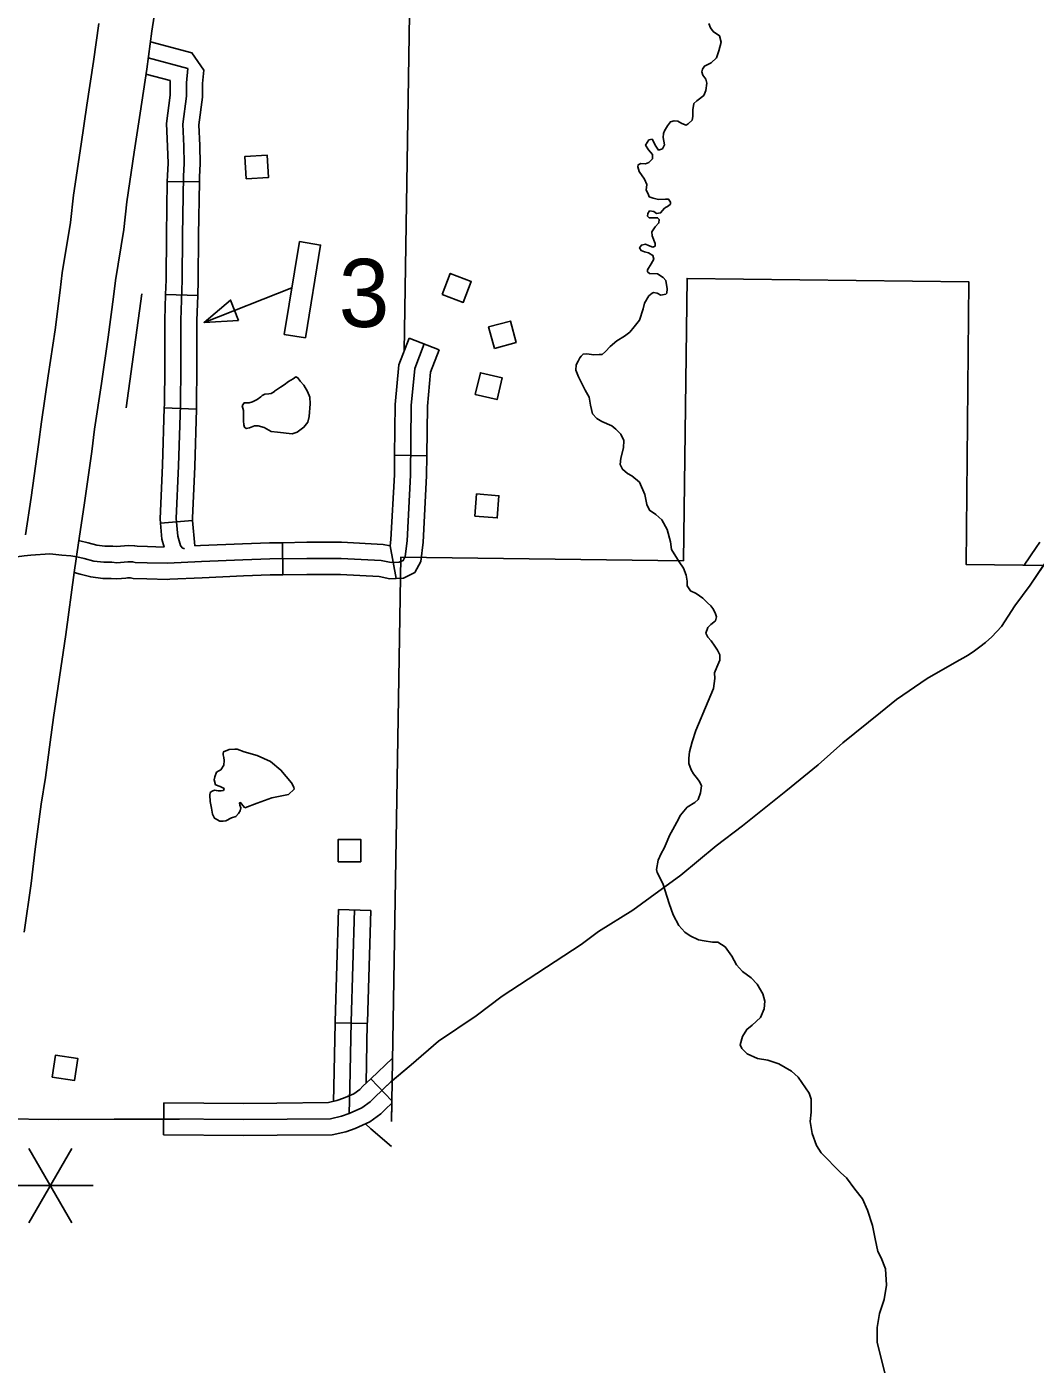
# Model space of a CAD drawing. Extents: x 61396 to 64680, y 55472 to 57605.
# Drawn here: x 63058.6 to 63205.3, y 56330.1 to 56524.6 of the extents above; entities that cross this region are included whole.
import ezdxf

# ---------------------------------------------------------------- set-up
doc = ezdxf.new("R2010")
doc.units = 0
for name, color, linetype in [('15', 7, 'Continuous'), ('31', 7, 'Continuous'), ('32', 7, 'Continuous'), ('33', 7, 'Continuous'), ('34', 7, 'Continuous'), ('35', 7, 'Continuous'), ('48', 7, 'Continuous'), ('5', 7, 'Continuous'), ('56', 7, 'Continuous'), ('6', 7, 'Continuous')]:
    doc.layers.add(name, color=color, linetype=linetype)

msp = doc.modelspace()

# ---------------------------------------------------------------- linework, layer by layer
at = {"layer": '15'}
for points in [[(63077.66, 56529.26), (63076.83, 56523.94), (63076.08, 56518.41), (63075.12, 56512.02), (63074.28, 56506.36), (63073.17, 56499.11), (63072.75, 56495.1), (63071.54, 56487.7), (63071.26, 56485.31), (63070.5, 56479.43), (63069.5, 56472.69), (63068.5, 56466.07), (63068.09, 56462.8), (63067, 56455.01), (63066.17, 56449.55), (63065.55, 56445.21), (63064.3, 56436.22), (63063.21, 56428.7), (63062.51, 56424.15), (63062.06, 56420.57), (63061.38, 56415.43), (63060.75, 56411.55), (63059.85, 56404.97), (63059.27, 56400.01), (63058.26, 56392.9)], [(63058.44, 56450.7), (63059.27, 56456.14), (63060.35, 56463.83), (63060.77, 56467.14), (63061.77, 56473.84), (63062.76, 56480.5), (63063.51, 56486.27), (63063.8, 56488.8), (63065.01, 56496.14), (63065.42, 56500.11), (63066.56, 56507.52), (63067.39, 56513.17), (63068.34, 56519.52), (63069.1, 56525.07)]]:
    msp.add_lwpolyline(points, dxfattribs=at)
at = {"layer": '31'}
msp.add_line((63078.55, 56368.11), (63078.51, 56363.42), dxfattribs=at)
for points in [[(63205.95, 56449.65), (63205.45, 56448.88), (63203.71, 56446.31), (63209.33, 56446.24)], [(63046.7, 56442.08), (63047.5, 56442.34), (63048.97, 56443.14), (63052.37, 56445.59), (63053.66, 56446.32), (63054.54, 56446.81), (63055.19, 56447.16), (63055.94, 56447.34), (63056.52, 56447.43), (63057.21, 56447.52), (63058.25, 56447.65), (63059.23, 56447.72), (63061.99, 56447.93)], [(63105.55, 56366.56), (63107.36, 56367.35), (63108.6, 56368.25), (63109.17, 56368.84), (63111.58, 56371.13), (63114.52, 56373.62), (63118.5, 56377.08), (63124, 56380.77), (63127.78, 56383.63), (63139.28, 56391.14), (63141.77, 56392.99), (63146.79, 56396.12), (63149.29, 56397.97), (63153.75, 56401.18), (63158.89, 56405.48), (63162.71, 56408.38), (63169.02, 56413.4), (63173.73, 56417.26), (63177.34, 56420.47), (63182.81, 56424.85), (63185.14, 56426.74), (63189.6, 56429.79), (63193.54, 56432.08), (63195.55, 56433.21), (63196.48, 56433.81), (63197.24, 56434.41), (63198.09, 56435.06), (63199.01, 56435.86), (63200.38, 56437.35), (63202.35, 56440.36), (63204.56, 56443.37), (63207.41, 56447.59)], [(63108.67, 56371.6), (63111.84, 56374.6)], [(63108.67, 56371.6), (63107.52, 56370.51), (63107.06, 56370.03), (63106.19, 56369.4), (63104.69, 56368.75), (63103.74, 56368.41), (63102.51, 56368.13), (63095.01, 56368.06)], [(63111.73, 56368.04), (63111.74, 56368.38), (63108.67, 56371.6)], [(63105.55, 56366.56), (63107.36, 56367.35), (63108.6, 56368.25), (63109.17, 56368.84), (63111.78, 56371.32)], [(63095.01, 56368.06), (63090.19, 56368.01), (63078.55, 56368.11)], [(63095.05, 56363.37), (63103.06, 56363.45), (63105.05, 56363.9), (63106.41, 56364.38), (63108.53, 56365.31), (63110.14, 56366.48), (63110.82, 56367.17), (63111.73, 56368.04)], [(63078.53, 56365.77), (63090.2, 56365.66), (63102.79, 56365.79)], [(63102.79, 56365.79), (63104.4, 56366.15), (63105.55, 56366.56)], [(63102.79, 56365.79), (63104.4, 56366.15), (63105.55, 56366.56)], [(63078.51, 56363.42), (63090.2, 56363.32), (63095.05, 56363.37)]]:
    msp.add_lwpolyline(points, dxfattribs=at)
at = {"layer": '32'}
for p, q in [((63076.3, 56520.06), (63082.05, 56518.52)), ((63079.07, 56502.11), (63083.76, 56502.03)), ((63078.82, 56485.65), (63083.51, 56485.49)), ((63114.25, 56479.31), (63118.62, 56477.62)), ((63078.64, 56469.15), (63083.33, 56469)), ((63112.13, 56462.27), (63116.82, 56462.21)), ((63078.09, 56452.39), (63082.76, 56452.78)), ((63095.81, 56449.56), (63095.86, 56444.88)), ((63111.5, 56449.09), (63112.38, 56444.35)), ((63103.98, 56396.22), (63108.66, 56396.08)), ((63103.48, 56379.71), (63108.16, 56379.61))]:
    msp.add_line(p, q, dxfattribs=at)
for points in [[(63076.62, 56522.4), (63082.66, 56520.78), (63084.39, 56518.3)], [(63075.97, 56517.72), (63079.51, 56516.77)], [(63082.05, 56518.52), (63081.86, 56516.43), (63081.86, 56514.48), (63081.33, 56510.43), (63081.48, 56507.24), (63081.52, 56504.72), (63081.43, 56502.86), (63081.29, 56494.29), (63081.24, 56487.73), (63081.05, 56481.92), (63081.05, 56475.11), (63081, 56469.59), (63080.71, 56460.74), (63080.38, 56453.07), (63080.6, 56450.51), (63081.01, 56449.13), (63081.25, 56448.83), (63081.56, 56448.67)], [(63084.39, 56518.3), (63084.2, 56516.32), (63084.2, 56514.33), (63083.68, 56510.33), (63083.82, 56507.32), (63083.87, 56504.68), (63083.77, 56502.78), (63083.76, 56502.03)], [(63079.51, 56516.77), (63079.51, 56514.63), (63078.98, 56510.53), (63079.13, 56507.17), (63079.18, 56504.76), (63079.09, 56502.94), (63079.07, 56502.11)], [(63079.07, 56502.11), (63078.94, 56494.32), (63078.89, 56487.77), (63078.82, 56485.65)], [(63083.76, 56502.03), (63083.63, 56494.27), (63083.58, 56487.68), (63083.51, 56485.49)], [(63078.82, 56485.65), (63078.7, 56481.96), (63078.7, 56475.12), (63078.66, 56469.64), (63078.64, 56469.15)], [(63083.51, 56485.49), (63083.39, 56481.88), (63083.39, 56475.1), (63083.34, 56469.54), (63083.33, 56469)], [(63114.25, 56479.31), (63112.76, 56475.44), (63112.22, 56469.66), (63112.13, 56462.27)], [(63116.44, 56478.46), (63115.06, 56474.9), (63114.56, 56469.53), (63114.44, 56459.36), (63113.94, 56449.84), (63113.69, 56447.56), (63113.38, 56446.99), (63112.81, 56446.71), (63111.65, 56446.67), (63110.16, 56446.97), (63104.34, 56447.26), (63099.37, 56447.26), (63093.99, 56447.2), (63090.08, 56447.07), (63084.03, 56446.81), (63079.12, 56446.56), (63076.15, 56446.65), (63074.42, 56446.69), (63074.02, 56446.78), (63073.33, 56446.79)], [(63118.62, 56477.62), (63117.37, 56474.36), (63116.91, 56469.41), (63116.82, 56462.21)], [(63078.64, 56469.15), (63078.37, 56460.83), (63078.03, 56453.03), (63078.09, 56452.39)], [(63083.33, 56469), (63083.06, 56460.65), (63082.73, 56453.12), (63082.76, 56452.78)], [(63112.13, 56462.27), (63112.1, 56459.43), (63111.6, 56450.02), (63111.5, 56449.09)], [(63116.82, 56462.21), (63116.78, 56459.28), (63116.28, 56449.65), (63115.97, 56446.83), (63115.07, 56445.22), (63113.41, 56444.39), (63112.38, 56444.35)], [(63078.09, 56452.39), (63078.28, 56450.06), (63078.63, 56448.92)], [(63082.76, 56452.78), (63083.07, 56449.11)], [(63066.21, 56449.84), (63066.35, 56449.83), (63067.57, 56449.53), (63068.85, 56449.2), (63069.99, 56449.05), (63071.14, 56449.05), (63071.76, 56448.99), (63073.37, 56449.13)], [(63095.81, 56449.56), (63093.94, 56449.54), (63089.99, 56449.41), (63083.92, 56449.16), (63083.07, 56449.11)], [(63111.5, 56449.09), (63110.45, 56449.3), (63104.4, 56449.61), (63099.36, 56449.61), (63095.81, 56449.56)], [(63061.99, 56447.93), (63063.76, 56447.74), (63065.05, 56447.63), (63065.93, 56447.52), (63067, 56447.26), (63068.4, 56446.89), (63069.84, 56446.71), (63071.02, 56446.71), (63071.76, 56446.63), (63073.33, 56446.79)], [(63078.63, 56448.92), (63076.2, 56449), (63074.7, 56449.03), (63074.31, 56449.12), (63073.37, 56449.13)], [(63065.55, 56445.2), (63066.43, 56444.99), (63067.95, 56444.58), (63069.69, 56444.36), (63070.9, 56444.36), (63071.76, 56444.28), (63073.74, 56444.44)], [(63079.47, 56444.23), (63079.15, 56444.21), (63076.09, 56444.31), (63074.13, 56444.35), (63073.74, 56444.44), (63073.29, 56444.44)], [(63095.86, 56444.88), (63094.04, 56444.86), (63090.17, 56444.73), (63084.14, 56444.47), (63079.47, 56444.23)], [(63112.38, 56444.35), (63111.46, 56444.32), (63109.87, 56444.64), (63104.28, 56444.92), (63099.39, 56444.92), (63095.86, 56444.88)], [(63103.98, 56396.22), (63103.48, 56379.93), (63103.48, 56379.71)], [(63106.32, 56396.15), (63105.83, 56379.87), (63105.62, 56370.31), (63105.55, 56366.56)], [(63108.66, 56396.08), (63108.17, 56379.81), (63108.16, 56379.61)], [(63103.48, 56379.71), (63103.28, 56370.35), (63103.24, 56368.29)], [(63108.16, 56379.61), (63107.98, 56370.94)]]:
    msp.add_lwpolyline(points, dxfattribs=at)
at = {"layer": '33'}
for points in [[(63206.52, 56446.27), (63204.56, 56443.37), (63202.35, 56440.36), (63200.38, 56437.35), (63199.01, 56435.86), (63198.09, 56435.06), (63197.24, 56434.41), (63196.48, 56433.81), (63195.55, 56433.21), (63193.54, 56432.08), (63189.6, 56429.79), (63185.14, 56426.74), (63182.81, 56424.85), (63177.34, 56420.47), (63173.73, 56417.26), (63169.02, 56413.4), (63162.71, 56408.38), (63158.89, 56405.48), (63153.75, 56401.18), (63149.29, 56397.97), (63146.79, 56396.12), (63141.77, 56392.99), (63139.28, 56391.14), (63127.78, 56383.63), (63124, 56380.77), (63118.5, 56377.08), (63114.52, 56373.62), (63111.78, 56371.3)], [(63050.7, 56365.95), (63051.63, 56365.89), (63052.75, 56365.86), (63054.55, 56365.76), (63063.27, 56365.66), (63071.35, 56365.72), (63080.84, 56365.74)]]:
    msp.add_lwpolyline(points, dxfattribs=at)
at = {"layer": '34'}
msp.add_lwpolyline([(63107.88, 56365.02), (63108.66, 56364.32), (63111.66, 56361.75)], dxfattribs=at)
at = {"layer": '35'}
for points in [[(63157.84, 56525.07), (63158.06, 56524.42), (63158.44, 56523.92), (63159.36, 56523.28), (63159.65, 56522.34), (63159.28, 56521.11), (63158.95, 56520.05), (63158.15, 56519.35), (63157.19, 56518.87), (63156.91, 56518.43), (63156.82, 56518.02), (63156.98, 56517.55), (63157.42, 56516.99), (63157.55, 56516.4), (63157.41, 56515.33), (63157.11, 56514.61), (63156.27, 56513.95), (63156.11, 56513.82), (63155.65, 56513.41), (63155.5, 56512.5), (63155.51, 56511.56), (63155.43, 56511.02), (63154.84, 56510.49), (63154.53, 56510.3), (63153.9, 56510.54), (63153.3, 56510.85), (63152.77, 56510.93), (63152.24, 56510.77), (63151.81, 56510.2), (63151.38, 56509.45), (63151.24, 56509.09), (63151.19, 56508.51), (63151.4, 56507.44), (63151.07, 56506.82), (63150.53, 56506.65), (63150.12, 56507.23), (63149.58, 56508.22), (63149.09, 56508.14)], [(63149.09, 56508.14), (63148.64, 56507.35), (63149.07, 56506.69), (63149.63, 56505.99), (63149.63, 56505.38), (63149.11, 56504.86), (63148.6, 56504.67), (63147.94, 56504.72), (63147.56, 56504.53), (63147.52, 56504.2), (63147.7, 56503.54), (63148.5, 56502.42), (63148.83, 56501.66), (63148.74, 56500.82), (63149.02, 56500.3), (63149.16, 56499.88), (63149.72, 56499.64), (63150.52, 56499.46), (63151.51, 56499.5), (63151.98, 56499.5), (63152.26, 56499.08), (63152.26, 56498.8), (63151.98, 56498.56), (63151.37, 56498.19), (63150.81, 56497.53), (63150.2, 56497.44), (63149.82, 56497.72), (63149.21, 56497.81), (63148.97, 56497.44), (63148.93, 56497.06), (63149.16, 56496.78), (63149.68, 56496.78), (63150.38, 56496.82), (63150.62, 56496.54), (63150.57, 56496.07), (63150.01, 56495.51), (63149.54, 56494.76), (63149.58, 56494.19), (63150.05, 56493.06), (63150.01, 56492.69), (63149.68, 56492.55), (63149.07, 56492.78), (63148.6, 56492.97), (63148.03, 56492.83), (63147.75, 56492.45), (63147.99, 56492.03), (63148.5, 56491.84), (63149.07, 56491.7), (63149.68, 56491.33), (63149.82, 56490.81), (63149.44, 56490.1), (63148.92, 56489.26), (63148.93, 56488.93)], [(63148.93, 56488.93), (63149.19, 56488.7), (63150.39, 56488.66), (63151.21, 56488.12), (63151.6, 56487.67), (63151.79, 56486.46), (63151.72, 56485.83), (63151.56, 56485.7), (63150.83, 56485.57), (63150.31, 56485.87), (63149.78, 56485.94), (63149.6, 56485.87), (63149.11, 56485.45), (63148.46, 56484.39), (63148.27, 56483.57), (63147.73, 56481.93), (63146.99, 56480.93), (63146.33, 56480.19), (63145.57, 56479.6), (63144.47, 56478.9), (63143.5, 56478.08), (63142.8, 56477.37), (63142.32, 56476.95), (63141.88, 56476.93), (63141.13, 56476.88), (63140.07, 56477), (63139.54, 56476.98), (63139.27, 56476.69), (63139.06, 56476.46), (63138.83, 56475.95), (63138.56, 56475.41), (63138.5, 56474.63), (63138.87, 56473.7), (63139.84, 56471.76), (63140.41, 56470.72), (63140.64, 56469.56), (63140.93, 56468.32), (63141.55, 56467.62), (63142.28, 56467.18), (63143.71, 56466.54), (63144.32, 56466.06), (63145.03, 56465.36), (63145.47, 56464.44), (63145.41, 56463.34), (63145.03, 56461.86), (63144.96, 56460.95), (63145.3, 56460.24), (63145.98, 56459.61), (63146.65, 56459.28), (63147.77, 56458.35), (63148.52, 56456.59), (63148.82, 56455.13), (63149.22, 56454.27), (63150.12, 56453.64), (63151.02, 56452.86), (63151.79, 56451.48), (63152.25, 56449.68), (63152.39, 56448.56), (63153.51, 56446.78), (63154.13, 56445.86), (63154.54, 56444.84), (63154.7, 56443.94), (63154.69, 56443.28), (63155.15, 56442.58), (63156.01, 56442.17), (63156.94, 56441.48), (63157.65, 56440.82), (63158.1, 56440.39), (63158.4, 56439.97), (63158.76, 56439.38), (63158.97, 56438.76), (63158.8, 56438.2), (63158.1, 56437.64), (63157.68, 56437.22), (63157.4, 56436.39), (63157.7, 56435.81), (63158.18, 56435.29), (63158.71, 56434.53), (63159.07, 56433.95), (63159.41, 56433.24), (63159.41, 56432.49), (63159, 56431.47), (63158.66, 56430.61), (63158.69, 56429.8), (63158.52, 56428.36), (63157.74, 56426.51), (63155.95, 56422.26), (63155.42, 56420.58), (63155.03, 56419.16), (63154.94, 56418.21)], [(63154.94, 56418.21), (63154.9, 56417.46), (63155.24, 56416.5), (63155.58, 56415.95), (63155.97, 56415.46), (63156.49, 56414.82), (63156.76, 56414.18), (63156.64, 56413.17), (63156.3, 56412.22), (63155.78, 56411.76), (63154.68, 56411.07), (63153.72, 56409.91), (63153.17, 56408.92), (63152.61, 56407.83), (63152.11, 56406.97), (63151.79, 56406.15), (63151.33, 56405.13), (63150.92, 56404.36), (63150.45, 56403.38), (63150.22, 56402.02), (63150.3, 56401.6)], [(63150.3, 56401.6), (63151.12, 56400), (63152.06, 56397.08), (63152.66, 56395.44), (63153.47, 56393.87), (63154.34, 56392.9), (63155.14, 56392.39), (63156.35, 56391.81), (63157.17, 56391.65), (63158.36, 56391.47), (63159.14, 56391.47), (63160.19, 56390.78), (63161.18, 56389.41), (63161.84, 56388.18), (63162.75, 56387.18), (63163.97, 56386.28), (63164.88, 56385.34), (63165.67, 56383.96), (63165.96, 56382.87), (63165.88, 56381.77), (63165.36, 56380.5), (63164.12, 56379.4), (63163.36, 56378.78), (63162.74, 56377.75), (63162.4, 56376.55), (63162.61, 56375.99), (63163.39, 56375.24), (63164.91, 56374.54), (63166.42, 56374.28), (63167.99, 56373.77), (63168.95, 56373.24), (63169.84, 56372.71), (63170.81, 56371.83), (63172.42, 56369.48), (63172.7, 56368.64), (63172.7, 56366.73), (63172.56, 56365.38), (63172.84, 56363.61), (63173.49, 56361.87), (63174.16, 56360.8), (63177.04, 56357.9), (63177.84, 56357.17), (63179.08, 56355.52), (63180.16, 56354.12), (63180.91, 56352.49), (63181.61, 56350.26), (63182.02, 56348.33), (63182.43, 56346.47), (63182.9, 56345.54), (63183.54, 56343.94), (63183.66, 56341.56), (63183.32, 56339.48), (63182.64, 56337.46), (63182.31, 56335.41), (63182.29, 56333.22), (63183.44, 56328.81)]]:
    msp.add_lwpolyline(points, dxfattribs=at)
for points in [[(63089.98, 56469.47), (63090.16, 56468.77), (63090.16, 56467.96), (63090.16, 56467.27), (63090.2, 56466.72), (63090.31, 56466.35), (63090.57, 56466.16), (63091.01, 56466.24), (63091.74, 56466.57), (63092.29, 56466.57), (63093.18, 56466.31), (63094.2, 56465.72), (63095.12, 56465.65), (63097.25, 56465.39), (63097.95, 56465.61), (63098.94, 56466.35), (63099.5, 56467.08), (63099.72, 56467.89), (63099.86, 56469.73), (63099.79, 56470.72), (63099.46, 56471.53), (63098.94, 56472.48), (63098.39, 56473.03), (63098.06, 56473.51), (63097.77, 56473.66), (63097.36, 56473.4), (63096.7, 56473), (63096.08, 56472.52), (63095.56, 56472.19), (63094.68, 56471.6), (63094.65, 56471.53), (63094.2, 56471.27), (63093.84, 56471.2), (63093.25, 56471.16), (63092.88, 56470.98), (63092.66, 56470.76), (63092.15, 56470.39), (63091.49, 56470.02), (63090.97, 56469.91), (63090.24, 56469.88)], [(63090.35, 56410.99), (63092.15, 56411.66), (63094.29, 56412.46), (63096.7, 56412.94), (63097.51, 56413.69), (63097.46, 56413.98), (63097.13, 56414.64), (63095.61, 56416.49), (63094.1, 56417.72), (63092.15, 56418.62), (63090.26, 56419.14), (63089.22, 56419.52), (63088.89, 56419.52), (63088.08, 56419.47), (63087.23, 56419.14), (63087.18, 56418.9), (63087.18, 56418.71), (63087.32, 56418.33), (63087.37, 56417.86), (63087.28, 56417.2), (63086.85, 56416.53), (63086.57, 56416.39), (63086.23, 56416.16), (63086, 56415.49), (63085.9, 56415.07), (63086.09, 56414.36), (63086.75, 56414.12), (63087.37, 56413.79), (63087.23, 56413.5), (63086.9, 56413.46), (63086.47, 56413.46), (63086.23, 56413.5), (63085.95, 56413.55), (63085.62, 56413.41), (63085.33, 56413.22), (63085.24, 56412.84), (63085.33, 56411.94), (63085.52, 56410.95), (63085.67, 56410.09), (63085.95, 56409.48), (63086.71, 56409.05), (63087.18, 56409.05), (63087.61, 56409.1), (63088.41, 56409.53), (63089.03, 56409.76), (63089.41, 56410.19), (63089.69, 56410.57), (63089.79, 56410.99), (63089.64, 56411.37), (63089.6, 56411.7), (63089.74, 56411.75), (63089.83, 56411.61)]]:
    msp.add_lwpolyline(points, close=True, dxfattribs=at)
at = {"layer": '48'}
for p, q in [((63065.18, 56361.46), (63058.93, 56350.63)), ((63058.93, 56361.46), (63065.18, 56350.63)), ((63055.81, 56356.05), (63068.31, 56356.05))]:
    msp.add_line(p, q, dxfattribs=at)
at = {"layer": '5'}
for points in [[(63114.37, 56529.5), (63113.52, 56477.42)], [(63111.73, 56368.04), (63111.69, 56365.39)]]:
    msp.add_lwpolyline(points, dxfattribs=at)
at = {"layer": '56'}
for points in [[(63090.56, 56502.47), (63090.33, 56505.71), (63093.59, 56505.94), (63093.81, 56502.69)], [(63098.29, 56493.35), (63101.38, 56492.85), (63099.17, 56479.36), (63096.08, 56479.86)], [(63119.07, 56485.66), (63120.22, 56488.71), (63123.27, 56487.55), (63122.12, 56484.51)], [(63089.45, 56481.86), (63088.28, 56484.83), (63084.42, 56481.6)], [(63126.64, 56477.82), (63125.81, 56480.96), (63128.97, 56481.79), (63129.8, 56478.65)], [(63123.86, 56471.1), (63124.61, 56474.27), (63127.78, 56473.52), (63127.04, 56470.36)], [(63123.8, 56453.4), (63124.05, 56456.64), (63127.31, 56456.39), (63127.05, 56453.15)], [(63103.93, 56403.15), (63103.93, 56406.4), (63107.2, 56406.4), (63107.2, 56403.15)], [(63062.35, 56371.84), (63062.84, 56375.05), (63066.06, 56374.56), (63065.57, 56371.34)]]:
    msp.add_lwpolyline(points, close=True, dxfattribs=at)
for points in [[(63097.19, 56486.61), (63084.42, 56481.6)], [(63075.38, 56485.75), (63073.08, 56469.17)]]:
    msp.add_lwpolyline(points, dxfattribs=at)
at = {"layer": '6'}
msp.add_lwpolyline([(63111.69, 56365.39), (63113.03, 56447.45), (63154.14, 56446.93), (63154.66, 56487.99), (63195.62, 56487.51), (63195.25, 56446.41), (63236.35, 56445.9), (63235.89, 56363.64), (63235.14, 56322.23), (63276.37, 56321.63), (63275.83, 56297.13)], dxfattribs=at)

# ---------------------------------------------------------------- texts
at = {"layer": '56'}
msp.add_text('3', height=9.9, dxfattribs=at).set_placement((63104.01, 56480.93))

doc.saveas('drawing.dxf')
